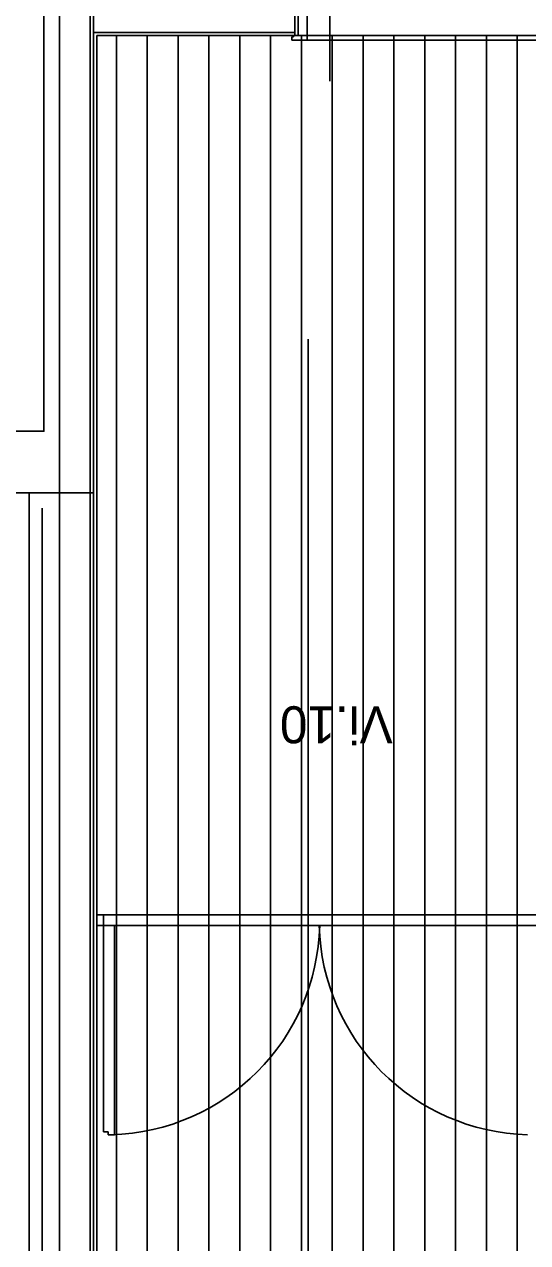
# Model space of a CAD drawing. Extents: x 1278 to 1356, y -253.7 to -224.
# Drawn here: x 1299.306 to 1300.938, y -239.071 to -235.119 of the extents above; entities that cross this region are included whole.
import ezdxf

# ---------------------------------------------------------------- set-up
doc = ezdxf.new("R2010")
doc.units = 0
for name, color, linetype in [('Level 1', 7, 'Continuous'), ('Level 10', 7, 'Continuous'), ('Level 13', 7, 'Continuous'), ('Level 4', 7, 'Continuous'), ('Level 40', 7, 'Continuous'), ('Level 65', 7, 'Continuous'), ('Level 66', 7, 'Continuous'), ('Level 67', 7, 'Continuous'), ('Level 70', 7, 'Continuous'), ('Level 93', 7, 'Continuous')]:
    doc.layers.add(name, color=color, linetype=linetype)

msp = doc.modelspace()

# ---------------------------------------------------------------- linework, layer by layer
at = {"layer": 'Level 1'}
for p, q in [((1300.1831, -235.0652), (1300.1831, -235.1552)), ((1299.5304, -235.1452), (1300.1831, -235.1452)), ((1297.7633, -236.639), (1299.5304, -236.639)), ((1299.3633, -239.304), (1299.3633, -236.689))]:
    msp.add_line(p, q, dxfattribs=at)
at = {"layer": 'Level 10'}
for p, q in [((1299.6041, -243.574), (1299.6041, -235.1552)), ((1299.7041, -243.574), (1299.7041, -235.1552)), ((1299.8041, -243.574), (1299.8041, -235.1552)), ((1299.9041, -243.574), (1299.9041, -235.1552)), ((1300.0041, -243.574), (1300.0041, -235.1552)), ((1300.1041, -243.574), (1300.1041, -235.1552)), ((1300.2041, -243.574), (1300.2041, -235.1552)), ((1300.9731, -235.1552), (1300.2231, -235.1552)), ((1300.3041, -243.574), (1300.3041, -235.1552)), ((1300.4041, -243.574), (1300.4041, -235.1552)), ((1300.5041, -243.574), (1300.5041, -235.1552)), ((1300.6041, -243.574), (1300.6041, -235.1552)), ((1300.7041, -243.574), (1300.7041, -235.1552)), ((1300.8041, -243.574), (1300.8041, -235.1552)), ((1300.9041, -243.574), (1300.9041, -235.1552))]:
    msp.add_line(p, q, dxfattribs=at)
at = {"layer": 'Level 13'}
for p, q in [((1300.1931, -235.0652), (1300.1931, -235.1552)), ((1300.2231, -235.1552), (1300.2231, -235.0852)), ((1300.1781, -235.1602), (1300.1731, -235.1602)), ((1300.1731, -235.1602), (1300.1731, -235.1702)), ((1300.1731, -235.1702), (1300.2231, -235.1702)), ((1300.2231, -235.1552), (1300.1781, -235.1552)), ((1300.1781, -235.1552), (1300.1781, -235.1602)), ((1300.1931, -235.1552), (1300.2231, -235.1552)), ((1300.2231, -235.1702), (1300.2231, -235.1552)), ((1299.5627, -238.0075), (1299.5427, -238.0075)), ((1299.5627, -238.0075), (1299.5427, -238.0075)), ((1299.5627, -238.0075), (1299.5427, -238.0075)), ((1299.5627, -238.0425), (1299.5627, -238.0075)), ((1299.5627, -238.0425), (1299.5627, -238.0075)), ((1299.5627, -238.0425), (1299.5627, -238.0075)), ((1299.5627, -238.0425), (1299.5427, -238.0425)), ((1299.5627, -238.0425), (1299.5427, -238.0425)), ((1299.5627, -238.0425), (1299.5427, -238.0425)), ((1299.5627, -238.0425), (1299.5627, -238.7116)), ((1299.5627, -238.0425), (1299.5627, -238.7116)), ((1299.5627, -238.0425), (1299.5627, -238.7116)), ((1299.5977, -238.0425), (1299.5627, -238.0425)), ((1299.5977, -238.0425), (1299.5627, -238.0425)), ((1299.5977, -238.0425), (1299.5627, -238.0425)), ((1299.5977, -238.0425), (1299.5977, -238.7216)), ((1299.5977, -238.0425), (1299.5977, -238.7216)), ((1299.5977, -238.0425), (1299.5977, -238.7216)), ((1299.5777, -238.7116), (1299.5627, -238.7116)), ((1299.5777, -238.7116), (1299.5627, -238.7116)), ((1299.5777, -238.7116), (1299.5627, -238.7116)), ((1299.5777, -238.7116), (1299.5777, -238.7216)), ((1299.5777, -238.7116), (1299.5777, -238.7216)), ((1299.5777, -238.7116), (1299.5777, -238.7216)), ((1299.5977, -238.7216), (1299.5777, -238.7216)), ((1299.5977, -238.7216), (1299.5777, -238.7216)), ((1299.5977, -238.7216), (1299.5777, -238.7216))]:
    msp.add_line(p, q, dxfattribs=at)
at = {"layer": 'Level 4'}
for p, q in [((1300.2231, -235.1702), (1300.9731, -235.1702)), ((1300.9727, -238.0075), (1299.5514, -238.0075)), ((1300.9727, -238.0425), (1299.5864, -238.0425))]:
    msp.add_line(p, q, dxfattribs=at)
for centre, start, end in [((1299.5681, -238.0263), 271.6204, 358.6698), ((1300.9574, -238.0263), 181.3302, 268.3796)]:
    msp.add_arc(centre, 0.6955, start, end, dxfattribs=at)
at = {"layer": 'Level 65'}
for p, q in [((1299.5404, -235.1552), (1300.1831, -235.1552)), ((1299.5404, -243.574), (1299.5404, -235.1552))]:
    msp.add_line(p, q, dxfattribs=at)
at = {"layer": 'Level 66'}
msp.add_line((1299.5304, -243.584), (1299.5304, -232.264), dxfattribs=at)
for points in [[(1299.519, -234.744), (1299.519, -236.639), (1297.724, -236.639), (1297.724, -234.744), (1297.874, -234.744), (1297.874, -236.439), (1299.369, -236.439), (1299.369, -234.744)], [(1299.519, -243.774), (1299.3208, -243.774), (1299.3208, -236.639), (1299.519, -236.639)]]:
    msp.add_lwpolyline(points, close=True, dxfattribs=at)
at = {"layer": 'Level 67'}
msp.add_lwpolyline([(1300.1831, -235.0752), (1300.1831, -235.1452), (1299.5304, -235.1452), (1299.5304, -235.0752)], close=True, dxfattribs=at)
at = {"layer": 'Level 70'}
msp.add_line((1299.4199, -250.7923), (1299.4199, -225.5674), dxfattribs=at)
at = {"layer": 'Level 93'}
for p, q in [((1300.2965, -235.3039), (1300.2965, -224.3117)), ((1300.2265, -246.757), (1300.2265, -236.1407))]:
    msp.add_line(p, q, dxfattribs=at)

# ---------------------------------------------------------------- texts
at = {"layer": 'Level 40'}
msp.add_text('Vi.10', height=0.12, rotation=180, dxfattribs=at).set_placement((1300.5002, -237.3313))

doc.saveas('drawing.dxf')
